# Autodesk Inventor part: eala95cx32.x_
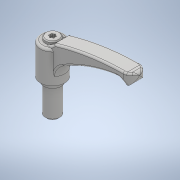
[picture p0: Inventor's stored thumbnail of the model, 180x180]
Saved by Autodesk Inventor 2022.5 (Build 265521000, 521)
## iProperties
Created: 2018-05
Part Number: eala95cx32.x_
Material: 一般
Document SubType Name: Modeling
Designer: imaocorp
Density: 1 g/cm^3
Appearance: 既定
Sending System: SOLIDWORKS 2016-2016286
MC: AMD64
MC_MODEL: AMD64 Family 21 Model 2 Stepping 0, AuthenticAMD
OS: Windows_NT
FRU: Parasolid Version 28.0, build 224,  7-29-2016
FORMAT: text
GUISE: transmit
KEY: eala95cx32
FILE: eala95cx32.x_t
DATE: Fri May 18 11:34:19 2018
Author: imaocorp
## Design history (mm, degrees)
feature "Base1"
node "ソリッド1"
